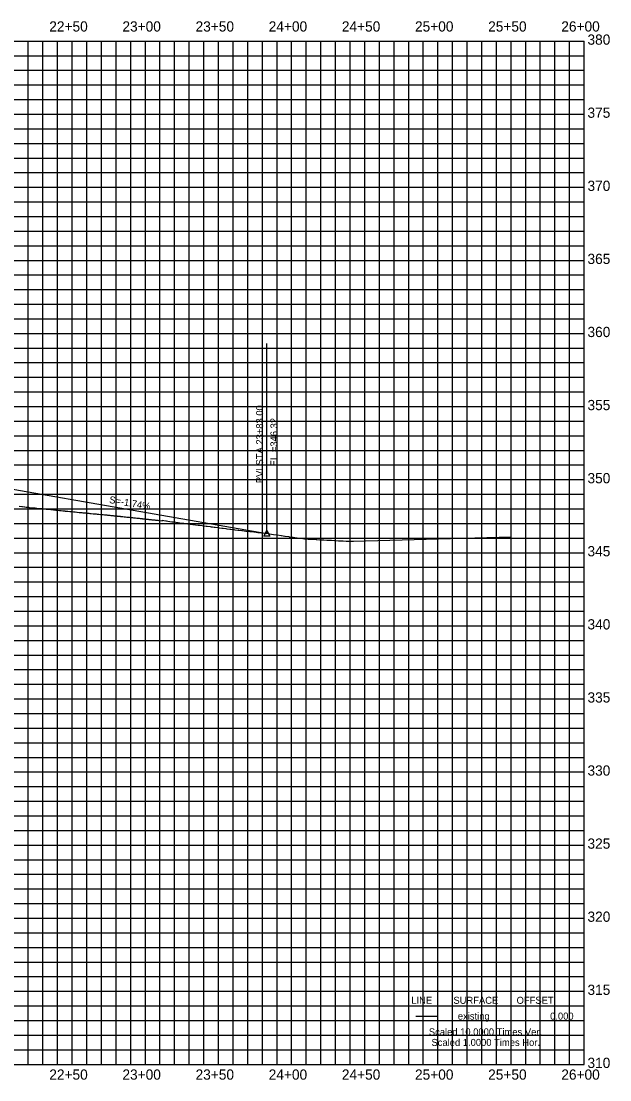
# Model space of a CAD drawing. Extents: x -797 to 1040, y -6256 to -5532.
# Drawn here: x 637 to 1040, y -6256 to -5532 of the extents above; entities that cross this region are included whole.
import ezdxf

# ---------------------------------------------------------------- set-up
doc = ezdxf.new("R2010")
doc.units = 0
for name, color, linetype in [('CT_Pro_Grid_Frame', 7, 'Continuous'), ('CT_Pro_screen_Major', 7, 'Continuous'), ('CT_Pro_screen_Minor', 7, 'Continuous'), ('HM-SMOD-USR DEF1', 7, 'Continuous'), ('HR-GMSC-HOR_VER ALN', 7, 'Continuous'), ('HR-GPRO-PVCPVIPVT LDR', 7, 'Continuous'), ('HR-GPRO-PVI SYMB', 7, 'Continuous'), ('HR-GPRO-PVI TXT', 7, 'Continuous'), ('HR-GPRO-STA_ELEV GRID TXT', 7, 'Continuous'), ('HR-GPRO-TAN GRADE TXT', 7, 'Continuous')]:
    doc.layers.add(name, color=color, linetype=linetype)

msp = doc.modelspace()

# ---------------------------------------------------------------- linework, layer by layer
at = {"layer": 'CT_Pro_Grid_Frame'}
for p, q in [((222.2, -5545.62), (1022.2, -5545.62)), ((1022.2, -6245.62), (1022.2, -5545.62)), ((222.2, -6245.62), (1022.2, -6245.62))]:
    msp.add_line(p, q, dxfattribs=at)
at = {"layer": 'CT_Pro_screen_Major'}
for p, q in [((672.2, -6245.62), (672.2, -5545.62)), ((722.2, -6245.62), (722.2, -5545.62)), ((772.2, -6245.62), (772.2, -5545.62)), ((822.2, -6245.62), (822.2, -5545.62)), ((872.2, -6245.62), (872.2, -5545.62)), ((922.2, -6245.62), (922.2, -5545.62)), ((972.2, -6245.62), (972.2, -5545.62)), ((222.2, -5595.62), (1022.2, -5595.62)), ((222.2, -5645.62), (1022.2, -5645.62)), ((222.2, -5695.62), (1022.2, -5695.62)), ((222.2, -5745.62), (1022.2, -5745.62)), ((222.2, -5795.62), (1022.2, -5795.62)), ((222.2, -5845.62), (1022.2, -5845.62)), ((222.2, -5895.62), (1022.2, -5895.62)), ((222.2, -5945.62), (1022.2, -5945.62)), ((222.2, -5995.62), (1022.2, -5995.62)), ((222.2, -6045.62), (1022.2, -6045.62)), ((222.2, -6095.62), (1022.2, -6095.62)), ((222.2, -6145.62), (1022.2, -6145.62)), ((222.2, -6195.62), (1022.2, -6195.62))]:
    msp.add_line(p, q, dxfattribs=at)
at = {"layer": 'CT_Pro_screen_Minor'}
for p, q in [((642.2, -6245.62), (642.2, -5545.62)), ((652.2, -6245.62), (652.2, -5545.62)), ((662.2, -6245.62), (662.2, -5545.62)), ((682.2, -6245.62), (682.2, -5545.62)), ((692.2, -6245.62), (692.2, -5545.62)), ((702.2, -6245.62), (702.2, -5545.62)), ((712.2, -6245.62), (712.2, -5545.62)), ((732.2, -6245.62), (732.2, -5545.62)), ((742.2, -6245.62), (742.2, -5545.62)), ((752.2, -6245.62), (752.2, -5545.62)), ((762.2, -6245.62), (762.2, -5545.62)), ((782.2, -6245.62), (782.2, -5545.62)), ((792.2, -6245.62), (792.2, -5545.62)), ((802.2, -6245.62), (802.2, -5545.62)), ((812.2, -6245.62), (812.2, -5545.62)), ((832.2, -6245.62), (832.2, -5545.62)), ((842.2, -6245.62), (842.2, -5545.62)), ((852.2, -6245.62), (852.2, -5545.62)), ((862.2, -6245.62), (862.2, -5545.62)), ((882.2, -6245.62), (882.2, -5545.62)), ((892.2, -6245.62), (892.2, -5545.62)), ((902.2, -6245.62), (902.2, -5545.62)), ((912.2, -6245.62), (912.2, -5545.62)), ((932.2, -6245.62), (932.2, -5545.62)), ((942.2, -6245.62), (942.2, -5545.62)), ((952.2, -6245.62), (952.2, -5545.62)), ((962.2, -6245.62), (962.2, -5545.62)), ((982.2, -6245.62), (982.2, -5545.62)), ((992.2, -6245.62), (992.2, -5545.62)), ((1002.2, -6245.62), (1002.2, -5545.62)), ((1012.2, -6245.62), (1012.2, -5545.62)), ((222.2, -5555.62), (1022.2, -5555.62)), ((222.2, -5565.62), (1022.2, -5565.62)), ((222.2, -5575.62), (1022.2, -5575.62)), ((222.2, -5585.62), (1022.2, -5585.62)), ((222.2, -5605.62), (1022.2, -5605.62)), ((222.2, -5615.62), (1022.2, -5615.62)), ((222.2, -5625.62), (1022.2, -5625.62)), ((222.2, -5635.62), (1022.2, -5635.62)), ((222.2, -5655.62), (1022.2, -5655.62)), ((222.2, -5665.62), (1022.2, -5665.62)), ((222.2, -5675.62), (1022.2, -5675.62)), ((222.2, -5685.62), (1022.2, -5685.62)), ((222.2, -5705.62), (1022.2, -5705.62)), ((222.2, -5715.62), (1022.2, -5715.62)), ((222.2, -5725.62), (1022.2, -5725.62)), ((222.2, -5735.62), (1022.2, -5735.62)), ((222.2, -5755.62), (1022.2, -5755.62)), ((222.2, -5765.62), (1022.2, -5765.62)), ((222.2, -5775.62), (1022.2, -5775.62)), ((222.2, -5785.62), (1022.2, -5785.62)), ((222.2, -5805.62), (1022.2, -5805.62)), ((222.2, -5815.62), (1022.2, -5815.62)), ((222.2, -5825.62), (1022.2, -5825.62)), ((222.2, -5835.62), (1022.2, -5835.62)), ((222.2, -5855.62), (1022.2, -5855.62)), ((222.2, -5865.62), (1022.2, -5865.62)), ((222.2, -5875.62), (1022.2, -5875.62)), ((222.2, -5885.62), (1022.2, -5885.62)), ((222.2, -5905.62), (1022.2, -5905.62)), ((222.2, -5915.62), (1022.2, -5915.62)), ((222.2, -5925.62), (1022.2, -5925.62)), ((222.2, -5935.62), (1022.2, -5935.62)), ((222.2, -5955.62), (1022.2, -5955.62)), ((222.2, -5965.62), (1022.2, -5965.62)), ((222.2, -5975.62), (1022.2, -5975.62)), ((222.2, -5985.62), (1022.2, -5985.62)), ((222.2, -6005.62), (1022.2, -6005.62)), ((222.2, -6015.62), (1022.2, -6015.62)), ((222.2, -6025.62), (1022.2, -6025.62)), ((222.2, -6035.62), (1022.2, -6035.62)), ((222.2, -6055.62), (1022.2, -6055.62)), ((222.2, -6065.62), (1022.2, -6065.62)), ((222.2, -6075.62), (1022.2, -6075.62)), ((222.2, -6085.62), (1022.2, -6085.62)), ((222.2, -6105.62), (1022.2, -6105.62)), ((222.2, -6115.62), (1022.2, -6115.62)), ((222.2, -6125.62), (1022.2, -6125.62)), ((222.2, -6135.62), (1022.2, -6135.62)), ((222.2, -6155.62), (1022.2, -6155.62)), ((222.2, -6165.62), (1022.2, -6165.62)), ((222.2, -6175.62), (1022.2, -6175.62)), ((222.2, -6185.62), (1022.2, -6185.62)), ((222.2, -6205.62), (1022.2, -6205.62)), ((222.2, -6215.62), (1022.2, -6215.62)), ((222.2, -6225.62), (1022.2, -6225.62)), ((222.2, -6235.62), (1022.2, -6235.62))]:
    msp.add_line(p, q, dxfattribs=at)
at = {"layer": 'HM-SMOD-USR DEF1'}
msp.add_line((907, -6212.62), (921.4, -6212.62), dxfattribs=at)
msp.add_lwpolyline([(636.02, -5863.89), (637.78, -5864.07), (638.11, -5864.11), (638.2, -5864.12), (639.58, -5864.26), (639.76, -5864.28), (640.68, -5864.38), (640.87, -5864.39), (642.28, -5864.54), (642.7, -5864.59), (642.83, -5864.6), (642.91, -5864.61), (644.95, -5864.82), (645.14, -5864.84), (645.24, -5864.85), (646.59, -5864.99), (646.78, -5865.01), (646.81, -5865.01), (647.71, -5865.11), (647.93, -5865.13), (649.71, -5865.31), (649.87, -5865.33), (651.19, -5865.47), (651.27, -5865.48), (651.52, -5865.5), (652.4, -5865.59), (652.65, -5865.62), (654.4, -5865.8), (654.58, -5865.82), (655.44, -5865.9), (655.77, -5865.94), (655.8, -5865.94), (657.53, -5866.12), (657.72, -5866.14), (659.43, -5866.31), (659.82, -5866.35), (660.27, -5866.39), (660.95, -5866.46), (661.7, -5866.54), (662.11, -5866.58), (663.6, -5866.73), (663.89, -5866.75), (664.76, -5866.84), (665.73, -5866.93), (665.93, -5866.95), (666.33, -5866.99), (667.25, -5867.08), (667.42, -5867.1), (668.79, -5867.23), (669.15, -5867.27), (669.26, -5867.28), (670.49, -5867.39), (670.87, -5867.43), (671.54, -5867.5), (671.79, -5867.52), (673.12, -5867.65), (673.76, -5867.7), (673.78, -5867.71), (674.31, -5867.76), (675.29, -5867.85), (675.7, -5867.89), (677, -5868.01), (677.28, -5868.04), (677.92, -5868.1), (678.25, -5868.13), (678.87, -5868.19), (679.46, -5868.25), (680.88, -5868.38), (681.18, -5868.41), (681.79, -5868.47), (682.75, -5868.56), (683.04, -5868.59), (683.66, -5868.65), (684.29, -5868.71), (685.22, -5868.8), (686.58, -5868.92), (687.02, -5868.97), (687.25, -5868.99), (687.32, -5869), (688.67, -5869.12), (689.28, -5869.19), (689.95, -5869.25), (690.47, -5869.3), (691.65, -5869.41), (691.74, -5869.42), (692.01, -5869.45), (692.59, -5869.51), (693.46, -5869.59), (694.19, -5869.66), (695.48, -5869.79), (695.86, -5869.83), (696.24, -5869.86), (696.7, -5869.91), (697.47, -5869.99), (697.9, -5870.03), (698.52, -5870.09), (699.31, -5870.17), (700.15, -5870.25), (700.56, -5870.29), (700.74, -5870.31), (701.17, -5870.36), (701.72, -5870.41), (702.63, -5870.5), (703, -5870.54), (703.73, -5870.62), (704.48, -5870.69), (704.96, -5870.74), (705.23, -5870.77), (705.39, -5870.79), (706.35, -5870.89), (706.83, -5870.94), (707.7, -5871.02), (708.65, -5871.12), (709.54, -5871.21), (709.73, -5871.23), (710.48, -5871.31), (711.1, -5871.38), (711.71, -5871.44), (712.12, -5871.49), (712.53, -5871.53), (713.07, -5871.59), (713.34, -5871.62), (714.17, -5871.7), (714.23, -5871.7), (714.63, -5871.75), (715.53, -5871.85), (716.48, -5871.94), (717.37, -5872.04), (718.02, -5872.1), (718.61, -5872.17), (718.73, -5872.18), (719, -5872.21), (719.44, -5872.26), (719.95, -5872.31), (720.21, -5872.34), (721.1, -5872.43), (721.96, -5872.53), (722.63, -5872.59), (723.2, -5872.66), (723.22, -5872.66), (723.66, -5872.7), (724.03, -5872.74), (724.53, -5872.8), (725.46, -5872.89), (725.7, -5872.92), (726.26, -5872.98), (726.73, -5873.03), (727.09, -5873.07), (727.58, -5873.12), (727.72, -5873.14), (728.53, -5873.22), (728.77, -5873.24), (729.13, -5873.28), (729.61, -5873.34), (730.58, -5873.43), (730.81, -5873.46), (731.52, -5873.54), (731.98, -5873.59), (732.22, -5873.61), (733.98, -5873.78), (734, -5873.46), (734.91, -5873.56), (734.92, -5873.67), (736.23, -5873.87), (736.71, -5873.92), (737.62, -5874.04), (738.9, -5874.23), (740.33, -5874.4), (741.21, -5874.51), (741.79, -5874.58), (743.03, -5874.76), (744.52, -5874.95), (745.71, -5875.12), (745.73, -5875.12), (747.26, -5875.31), (748.43, -5875.48), (750, -5875.67), (750.2, -5875.7), (751.13, -5875.84), (752.74, -5876.03), (753.82, -5876.19), (754.7, -5876.3), (755.47, -5876.39), (756.51, -5876.54), (758.21, -5876.75), (759.2, -5876.89), (759.2, -5876.89), (760.94, -5877.1), (761.89, -5877.24), (763.67, -5877.45), (763.69, -5877.46), (764.57, -5877.58), (766.41, -5877.8), (767.25, -5877.92), (768.19, -5878.03), (769.14, -5878.15), (769.93, -5878.26), (771.87, -5878.49), (772.61, -5878.59), (772.69, -5878.6), (774.59, -5878.83), (775.28, -5878.92), (777.18, -5879.15), (777.32, -5879.16), (777.94, -5879.25), (780.04, -5879.49), (780.61, -5879.57), (781.68, -5879.7), (782.76, -5879.82), (783.27, -5879.89), (785.48, -5880.14), (785.92, -5880.2), (786.18, -5880.23), (788.2, -5880.46), (788.58, -5880.52), (790.91, -5880.78), (791.22, -5880.82), (793.61, -5881.09), (793.87, -5881.13), (796.31, -5881.4), (796.51, -5881.43), (799.01, -5881.71), (799.15, -5881.73), (801.7, -5882.02), (801.78, -5882.03), (804.38, -5882.32), (804.42, -5882.32), (806.3, -5882.54), (807.05, -5882.65), (807.07, -5882.65), (809.7, -5883.06), (809.77, -5883.07), (812.35, -5883.46), (812.47, -5883.47), (815, -5883.85), (815.17, -5883.88), (817.65, -5884.24), (817.86, -5884.27), (820.3, -5884.63), (820.56, -5884.66), (822.95, -5885), (823.26, -5885.04), (825.61, -5885.38), (825.95, -5885.42), (828.26, -5885.74), (828.64, -5885.79), (830.92, -5886.11), (831.33, -5886.12), (833.58, -5886.28), (834.02, -5886.28), (836.23, -5886.44), (836.71, -5886.45), (838.89, -5886.59), (839.4, -5886.6), (841.55, -5886.74), (842.08, -5886.75), (844.21, -5886.89), (846.3, -5887.02), (846.87, -5887.03), (848.94, -5887.16), (849.52, -5887.16), (851.58, -5887.29), (852.18, -5887.29), (854.22, -5887.42), (854.84, -5887.42), (856.87, -5887.54), (857.5, -5887.55), (859.52, -5887.66), (860.16, -5887.67), (862.17, -5887.78), (862.82, -5887.78), (863.84, -5887.84), (864.51, -5887.84), (864.6, -5887.84), (972.18, -5884.83)], dxfattribs=at)
at = {"layer": 'HR-GMSC-HOR_VER ALN'}
msp.add_line((622.2, -5850.49), (805.2, -5882.41), dxfattribs=at)
at = {"layer": 'HR-GPRO-PVCPVIPVT LDR'}
msp.add_line((805.2, -5882.41), (805.2, -5752.41), dxfattribs=at)
at = {"layer": 'HR-GPRO-PVI SYMB'}
msp.add_lwpolyline([(805.2, -5880.41), (807.2, -5884.41), (803.2, -5884.41)], close=True, dxfattribs=at)

# ---------------------------------------------------------------- texts
at = {"layer": 'HR-GPRO-PVI TXT'}
for s, p in [('PVI STA.23+83.00', (802.7, -5848.07)), ('EL.=346.32', (812.5, -5836.47))]:
    msp.add_text(s, height=4.8, rotation=90, dxfattribs=at).set_placement(p)
at = {"layer": 'HR-GPRO-STA_ELEV GRID TXT'}
for s, height, p in [('22+50', 7, (656.53, -5539.12)), ('23+00', 7, (706.53, -5539.12)), ('23+50', 7, (756.53, -5539.12)), ('24+00', 7, (806.53, -5539.12)), ('24+50', 7, (856.53, -5539.12)), ('25+00', 7, (906.53, -5539.12)), ('25+50', 7, (956.53, -5539.12)), ('26+00', 7, (1006.53, -5539.12)), ('380', 7, (1024.44, -5548.12)), ('380', 7, (1024.44, -5548.12)), ('375', 7, (1024.44, -5598.12)), ('370', 7, (1024.44, -5648.12)), ('365', 7, (1024.44, -5698.12)), ('360', 7, (1024.44, -5748.12)), ('355', 7, (1024.44, -5798.12)), ('350', 7, (1024.44, -5848.12)), ('345', 7, (1024.44, -5898.12)), ('340', 7, (1024.44, -5948.12)), ('335', 7, (1024.44, -5998.12)), ('330', 7, (1024.44, -6048.12)), ('325', 7, (1024.44, -6098.12)), ('320', 7, (1024.44, -6148.12)), ('315', 7, (1024.44, -6198.12)), (' LINE ', 4.8, (902.2, -6204.22)), (' SURFACE ', 4.8, (931, -6204.22)), (' OFFSET ', 4.8, (974.2, -6204.22)), ('existing', 4.8, (935.8, -6215.02)), ('0.000', 4.8, (998.88, -6215.02)), ('Scaled 10.0000 Times Ver.', 4.8, (915.98, -6225.82)), ('Scaled 1.0000 Times Hor.', 4.8, (917.79, -6233.02)), ('310', 7, (1024.44, -6248.12)), ('22+50', 7, (656.53, -6256.12)), ('23+00', 7, (706.53, -6256.12)), ('23+50', 7, (756.53, -6256.12)), ('24+00', 7, (806.53, -6256.12)), ('24+50', 7, (856.53, -6256.12)), ('25+00', 7, (906.53, -6256.12)), ('25+50', 7, (956.53, -6256.12)), ('26+00', 7, (1006.53, -6256.12))]:
    msp.add_text(s, height=height, dxfattribs=at).set_placement(p)
at = {"layer": 'HR-GPRO-TAN GRADE TXT'}
msp.add_text('S=-1.74%', height=4.8, rotation=350.10796, dxfattribs=at).set_placement((697.25, -5861.55))

doc.saveas('drawing.dxf')
